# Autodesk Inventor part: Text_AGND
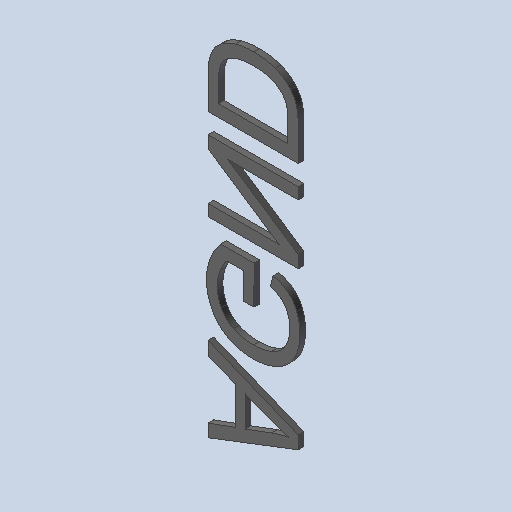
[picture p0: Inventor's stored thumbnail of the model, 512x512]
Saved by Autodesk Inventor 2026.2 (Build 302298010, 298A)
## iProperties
Created: 2026-10
Part Number: Text_AGND
Material: Générique
Document SubType Name: Modeling
Designer: mel
Density: 1 g/cm^3
Appearance: Par défaut
Author: mel
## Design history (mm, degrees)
feature "Base1"
feature "Base2"
feature "Base3"
feature "Base4"
node "Solide1"
node "Solide2"
node "Solide3"
node "Solide4"
